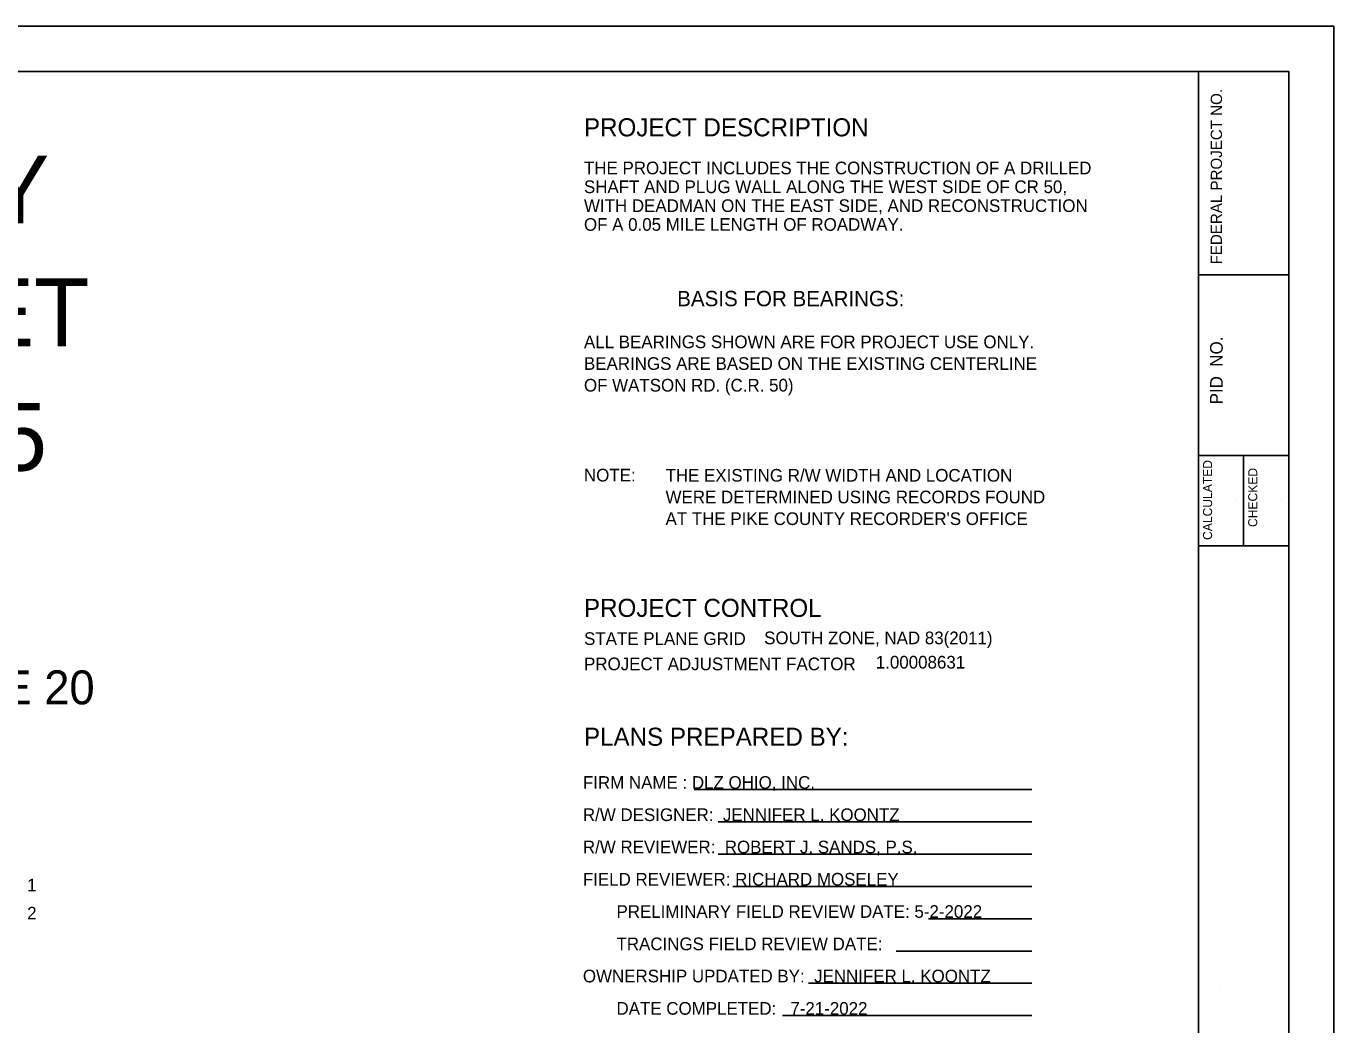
# Model space of a CAD drawing. Extents: x 5.6 to 39.6, y 0.7 to 22.7.
# Drawn here: x 25.08 to 39.55, y 11.66 to 22.71 of the extents above; entities that cross this region are included whole.
import ezdxf

# ---------------------------------------------------------------- set-up
doc = ezdxf.new("R2010")
doc.units = 0
for name, color, linetype in [('SH_Border', 7, 'Continuous'), ('SH_Cut_Line', 7, 'Continuous'), ('SH_Data', 7, 'Continuous'), ('SH_Text', 7, 'Continuous')]:
    doc.layers.add(name, color=color, linetype=linetype)

msp = doc.modelspace()

# ---------------------------------------------------------------- linework, layer by layer
at = {"layer": 'SH_Border'}
for p, q in [((38.052, 1.207), (38.052, 22.207)), ((38.052, 19.957), (39.052, 19.957)), ((38.052, 17.957), (39.052, 17.957)), ((38.052, 17.957), (39.052, 17.957)), ((38.552, 17.957), (38.552, 16.957)), ((38.052, 16.957), (39.052, 16.957))]:
    msp.add_line(p, q, dxfattribs=at)
msp.add_lwpolyline([(7.552, 22.207), (39.052, 22.207), (39.052, 1.207), (7.552, 1.207)], close=True, dxfattribs=at)
at = {"layer": 'SH_Cut_Line'}
msp.add_lwpolyline([(5.552, 0.707), (39.552, 0.707), (39.552, 22.707), (5.552, 22.707)], close=True, dxfattribs=at)
at = {"layer": 'SH_Data'}
for p, q in [((38.802, 21.082), (38.802, 21.082)), ((38.802, 18.957), (38.802, 18.957)), ((38.472, 17.461), (38.472, 17.461)), ((38.972, 17.461), (38.972, 17.461)), ((38.298, 12.082), (38.298, 12.082)), ((38.802, 12.082), (38.802, 12.082))]:
    msp.add_line(p, q, dxfattribs=at)
at = {"layer": 'SH_Text'}
for p, q in [((32.472, 14.259), (36.209, 14.259)), ((32.736, 13.901), (36.209, 13.901)), ((32.736, 13.544), (36.209, 13.544)), ((32.9, 13.187), (36.209, 13.187)), ((35.064, 12.83), (36.209, 12.83)), ((34.706, 12.473), (36.209, 12.473)), ((33.736, 12.116), (36.209, 12.116)), ((33.451, 11.758), (36.209, 11.758))]:
    msp.add_line(p, q, dxfattribs=at)

# ---------------------------------------------------------------- texts
at = {"layer": 'SH_Data'}
for s, height, p in [('FEDERAL PROJECT NO.', 0.125, (38.314, 20.071)), ('PID  NO.', 0.14, (38.322, 18.523)), ('CALCULATED', 0.1, (38.204, 17.022)), ('CHECKED', 0.1, (38.704, 17.165))]:
    msp.add_text(s, height=height, rotation=90, dxfattribs=at).set_placement(p)
for s, height, p in [('PROJECT DESCRIPTION', 0.2, (31.252, 21.488)), ('THE PROJECT INCLUDES THE CONSTRUCTION OF A DRILLED ', 0.14, (31.252, 21.068)), ('SHAFT AND PLUG WALL ALONG THE WEST SIDE OF CR 50, ', 0.14, (31.252, 20.86)), ('WITH DEADMAN ON THE EAST SIDE, AND RECONSTRUCTION ', 0.14, (31.252, 20.651)), ('OF A 0.05 MILE LENGTH OF ROADWAY.', 0.14, (31.252, 20.443))]:
    msp.add_text(s, height=height, dxfattribs=at).set_placement(p)
at = {"layer": 'SH_Text'}
for s, height, p in [('RIGHT OF WAY', 0.75, (17.979, 20.524)), ('LEGEND SHEET', 0.75, (18.032, 19.165)), ('BASIS FOR BEARINGS:', 0.17, (32.284, 19.608)), ('ALL BEARINGS SHOWN ARE FOR PROJECT USE ONLY.', 0.14, (31.252, 19.144)), ('BEARINGS ARE BASED ON THE EXISTING CENTERLINE        ', 0.14, (31.252, 18.904)), ('OF WATSON RD. (C.R. 50)                              ', 0.14, (31.252, 18.664)), ('PIK-CR50-2.55', 0.75, (18.508, 17.789)), ('NOTE:', 0.14, (31.252, 17.669)), ('THE EXISTING R/W WIDTH AND LOCATION', 0.14, (32.155, 17.667)), ('WERE DETERMINED USING RECORDS FOUND   ', 0.14, (32.155, 17.427)), ("AT THE PIKE COUNTY RECORDER'S OFFICE      ", 0.14, (32.155, 17.187)), ('PROJECT CONTROL', 0.2, (31.252, 16.17)), ('STATE PLANE GRID', 0.14, (31.253, 15.86)), ('SOUTH ZONE, NAD 83(2011)     ', 0.14, (33.246, 15.868)), ('PROJECT ADJUSTMENT FACTOR', 0.14, (31.253, 15.58)), ('1.00008631       ', 0.14, (34.482, 15.599)), ('         SECTION 16, TOWNSHIP 7, RANGE 20          ', 0.375, (15.498, 15.203)), ('PLANS PREPARED BY:', 0.2, (31.252, 14.744)), ('FIRM NAME : DLZ OHIO, INC.', 0.14, (31.24, 14.268)), ('R/W DESIGNER:  JENNIFER L. KOONTZ', 0.14, (31.24, 13.911)), ('R/W REVIEWER:  ROBERT J. SANDS, P.S.', 0.14, (31.24, 13.554)), ('FIELD REVIEWER: RICHARD MOSELEY', 0.14, (31.24, 13.197)), ('1     ', 0.14, (25.089, 13.134)), ('2     ', 0.14, (25.089, 12.822)), ('PRELIMINARY FIELD REVIEW DATE: 5-2-2022', 0.14, (31.612, 12.84)), ('TRACINGS FIELD REVIEW DATE:', 0.14, (31.612, 12.482)), ('OWNERSHIP UPDATED BY:  JENNIFER L. KOONTZ', 0.14, (31.24, 12.126)), ('DATE COMPLETED:   7-21-2022', 0.14, (31.612, 11.768))]:
    msp.add_text(s, height=height, dxfattribs=at).set_placement(p)

doc.saveas('drawing.dxf')
